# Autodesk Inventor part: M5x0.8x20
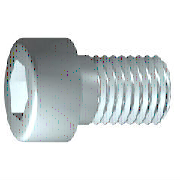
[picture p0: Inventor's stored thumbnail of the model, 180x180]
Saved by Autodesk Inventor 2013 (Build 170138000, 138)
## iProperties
IsCustomPart: 0
Created: 2015-11
Part Number: M5x0.8x20
Material: 스테인리스강
Description: 6각머리 태핑 나사
Document SubType Name: Modeling
Standard: KS B 1003
Designer: mdu
Standards Organization: KS
Language: ko-KR
Size Designation: M 5 x 20
Categories: <MemberInstance><Categories><Category DisplayName="조임쇠" InternalName="e4da775c-781d-43d5-af7c-5136215cf5a6" Mnemonic="FSTN"><Category DisplayName="볼트" InternalN
Density: 8.08 g/cm^3
Mass: 5.10181 g
Surface Area: 5.88237 cm^2
Volume: 0.631412 cm^3
Author: mdu
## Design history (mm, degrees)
sketch "스케치1"
  geometry: L1 (-1.167, 0)-(20, 0); L2 (20, 0)-(20, 2.5); L3 (20, 2.5)-(2, 2.5); L4 (2, 2.5)-(1.509, 2.5); L5 (1.509, 2.5)-(0, 2.5); L6 (0, 2.5)-(0, 4.25); L7 (0, 4.25)-(-5, 4.25); L8 (-5, 4.25)-(-5, 2.309); L9 (-5, 2.309)-(-2.5, 2.309); L10 (-2.5, 2.309)-(-1.167, 0); L11 (-10, 0)-(25, 0) reference; L12 (0, -0.85)-(0, 5.1) reference; L13 (2, 2.5)-(0, 2.5)
  constraints: 22 end point, 6 parallel, 2 collinear, 2 perpendicular, 1 horizontal, 1 point on line
  dimensions: "d1" = 18 distance from line of L3.end L2 (= GEL); "d2" = 0.49086 distance of L4.end L3.end (computed from GAL); "d3" = 5 distance between parallel lines of L8 L6 (= KOH); "d4" = 2.5 distance of L8.end L9.end (= INTI); "d5" = 60 deg angle of L10 L1; "d6" = 5 diameter of L3 L1 (= GD); "d7" = 5 diameter of L5 L1 (= BDM); "d8" = 4.6188 diameter of L9 L1 (= 1.1547 x SW); "d9" = 8.5 diameter of L7 L1 (= KOD); "d26" = 20 distance between parallel lines of L12 L2 (= NLG)
revolve "본체" sketch "스케치1" stored, may be unused: angle "d10" = 90 deg
sketch "스케치2"
  geometry: L1 (0, -5.95)-(0, 5.95) reference; L2 (-5.95, 0)-(5.95, 0) reference; L3 (2.309, 0)-(1.155, -2); L4 (1.155, -2)-(-1.155, -2); L5 (-1.155, -2)-(-2.309, 0); L6 (-2.309, 0)-(-1.155, 2); L7 (-1.155, 2)-(1.155, 2); L8 (1.155, 2)-(2.309, 0); 2 further points
  constraints: 12 end point, 1 coincident, 1 horizontal alignment, 1 point on line, 12 other
extrude "슬롯" join sketch "스케치2" stored distance "d11" = 10; taper "d12" = 0 deg
workplane "Work Plane1"
fillet "Fillet2" dims "d30" = 0.1 (= R)
body "Solid1"
fillet "모깎기1" dims "d17" = 0.5 (= RR)
feature "스레드" dims "d13" = 18 (= GEL), "d14" = 0
chamfer "모따기1" distance "d15" = 0.49076 (= -0.5 x SPD + 0.5 x GD); stored, may be unused: second distance "d16" = 0.49076 (= GUL), angle "d27" = 45 deg
other parameters: "GD" = 5 (= NND) [user parameter; used in 2 equation terms], "NLG" = 20 [user parameter; used in 1 equation term], "GEL" = 18 [user parameter; used in 2 equation terms], "KOD" = 8.5 [user parameter; used in 1 equation term], "KOH" = 5 [user parameter; used in 1 equation term], "INTI" = 2.5 [user parameter; used in 1 equation term], "GAL" = 0.49076 (= 0.61345 x PTC) [user parameter; used in 1 equation term], "GUL" = 0.49076 (= 0.61345 x PTC) [user parameter; used in 1 equation term], "BDM" = 5 (= NND) [user parameter; used in 1 equation term], "SW" = 4 [user parameter; used in 2 equation terms], "RR" = 0.5 [user parameter; used in 1 equation term], "SPD" = 4.01848 (= NND - 1.2269 x PTC) [user parameter; used in 1 equation term], "d19" = 0, "d28" = 0, "d29" = 0, "R" = 0.1 [user parameter; used in 1 equation term], "PHH" = 0.2 [user parameter], "GD1" = 4.01848 (= THREADDIA - 1.2269 x PTC) [user parameter], "THREADDIA" = 5 [user parameter; used in 1 equation term], "FAWI" = 45 deg [user parameter], "TPU" = 12.5 (computed from PTC) [user parameter], "PTC" = 0.8 [user parameter; used in 5 equation terms], "NND" = 5 [user parameter; used in 3 equation terms], "TOA" = 30 deg [user parameter], "E0" = 4.62 (= 1.155 x SW) [user parameter]
